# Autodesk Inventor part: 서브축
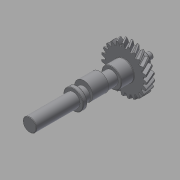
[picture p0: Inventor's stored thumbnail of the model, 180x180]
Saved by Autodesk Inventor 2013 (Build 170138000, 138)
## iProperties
Created: 2016-12
Part Number: 서브축
Material: 강철, 탄소
Document SubType Name: Modeling
Designer: mduedu
Categories: <?xml version="1.0" encoding="UTF-16"?> <MemberInstance><Categories><FamilyTemplate><FamilyTemplateParameter ValueType="xs:double" Id="1" ObjectReferenceKey="da
Density: 1 g/cm^3
CustomPartVersion: 1
Author: mduedu
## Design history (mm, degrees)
sketch "Sketch1"
  geometry: C1 r 28.558 at (0, 0)
  constraints: 1 centre point
  dimensions: "d0" = 57.11622 diameter of C1 (= da_da)
extrude "Extrusion1" new body sketch "Sketch1" distance "d1" = 10 (= da_b); taper "d2" = 0 deg
workplane "Work Plane2"
sketch "Sketch2"
  geometry: C1 r 28.558 at (0, 0) reference; C2 r 26.558 at (0, 0)
  constraints: 1 centre point, 1 coincident
  dimensions: "d3" = 53.11622 diameter of C2 (= da_dw)
feature "피치 지름" sketch "Sketch2" dims "d4" = 10, "d5" = 0
workplane "Work Plane8"
workplane "Work Plane9"
feature "스퍼 기어" dims "da_b" = 10, "da_d" = 53.11622, "da_aw" = 43.87862, "da_da" = 57.11622, "da_df" = 48.11622, "da_dw" = 53.11622, angle "da_beta" = 30 deg, "da_lefttooth" = 10, "da_righttooth" = 0
sketch "스케치3"
  geometry: C1 r 12.5 at (0, 0); 1 further point
  constraints: 1 centre point, 1 coincident
  dimensions: "d49" = 25 diameter of C1
extrude "돌출2" join sketch "스케치3" distance "d50" = 16; taper "d51" = 0 deg
sketch "스케치4"
  geometry: C1 r 8.5 at (0, 0); 1 further point
  constraints: 1 centre point, 1 coincident
  dimensions: "d52" = 17 diameter of C1
extrude "돌출3" join sketch "스케치4" distance "d53" = 103; taper "d54" = 0 deg
sketch "스케치5"
  geometry: C1 r 7.5 at (0, 0); 1 further point
  constraints: 1 centre point, 1 coincident
  dimensions: "d55" = 15 diameter of C1
extrude "돌출4" join sketch "스케치5" distance "d56" = 16; taper "d57" = 0 deg
sketch "스케치6"
  geometry: C1 r 4 at (0, 0); 1 further point
  constraints: 1 centre point, 1 coincident
  dimensions: "d58" = 8 diameter of C1
extrude "돌출5" join sketch "스케치6" distance "d59" = 7; taper "d60" = 0 deg
chamfer "모따기1" distance "d61" = 0.5; stored, may be unused: second distance "d62" = 2, angle "d63" = 45 deg
fillet "모깎기1" dims "d64" = 0.5
node "작업 평면11"
sketch "스케치7"
  geometry: C1 r 11.5 at (0, 3); C2 r 8.5 at (0, 0) reference; 1 further point
  constraints: 1 centre point, 1 tangent, 1 vertical alignment
  dimensions: "d66" = 3 distance of point (0, 0) C1.centre; "d67" = 23 diameter of C1 (derived)
extrude "돌출6" join sketch "스케치7" stored distance "d68" = 20; taper "d69" = 0 deg
node "작업 평면12"
sketch "스케치8"
  geometry: C1 r 12.5 at (0, 0) reference; 1 further point
extrude "돌출7" join sketch "스케치8" distance "d71" = 5; taper "d72" = 0 deg
chamfer "모따기2" distance "d73" = 0.5; stored, may be unused: second distance "d74" = 2, angle "d75" = 45 deg
body "Solid1"
body "Srf1"
other parameters: "d16" = 43.87862 (= da_aw), "d17" = 0, "d34" = 1.36591 (computed from da_z), "d39" = 0, "d41" = 0, "d43" = 43.87862 (= da_aw), "d46" = 43.87862 (= da_aw), "d47" = 0, "d48" = 0, "d65" = 25, "d70" = 48
